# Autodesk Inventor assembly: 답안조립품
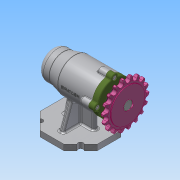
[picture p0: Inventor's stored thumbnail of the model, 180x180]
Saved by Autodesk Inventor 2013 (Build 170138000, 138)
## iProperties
Created: 2021-01
Part Number: 답안조립품
Document SubType Name: Assembly
Designer: Administrator
Author: Administrator
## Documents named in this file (12)
- C:\Users\Administrator\Desktop\710106V1026\답안조립품.iam
- C:\Users\Administrator\Desktop\710106V1026\본체.ipt
- C:\Users\Administrator\Desktop\710106V1026\베어링 6004.ipt
- C:\Users\Administrator\Desktop\710106V1026\오일 실.ipt
- C:\Users\Administrator\Desktop\710106V1026\커버.ipt
- C:\Users\Administrator\Desktop\710106V1026\볼트 M4.ipt
- C:\Users\Administrator\Desktop\710106V1026\베어링 51202.ipt
- C:\Users\Administrator\Desktop\710106V1026\어댑터슬리브.ipt
- C:\Users\Administrator\Desktop\710106V1026\축.ipt
- C:\Users\Administrator\Desktop\710106V1026\멈춤나사 M3.ipt
- C:\Users\Administrator\Desktop\710106V1026\스프로킷.ipt
- C:\Users\Administrator\Desktop\710106V1026\키 5 x 5 x 14.ipt
